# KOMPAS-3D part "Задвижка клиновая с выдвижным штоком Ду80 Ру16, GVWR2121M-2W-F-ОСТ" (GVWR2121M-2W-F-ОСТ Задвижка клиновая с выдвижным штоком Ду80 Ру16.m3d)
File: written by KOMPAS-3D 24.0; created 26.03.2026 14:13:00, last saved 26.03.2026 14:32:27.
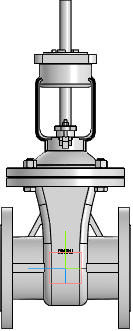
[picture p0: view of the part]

Document properties: Автор: R2D2; Полное имя файла: GVWR2121M-2W-F-ОСТ Задвижка клиновая с видвижным штоком Ду80 Ру16.cdw

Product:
- Part/product: Задвижка клиновая с выдвижным штоком Ду80 Ру16  | designation GVWR2121M-2W-F-ОСТ
    Масса: 24
    Раздел спецификации: Прочие изделия
    Форматы листов документа: A2
    Примечание: D040-07878

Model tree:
1. Операция без истории:1

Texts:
  GVWR2121M-2W-F-ОСТ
